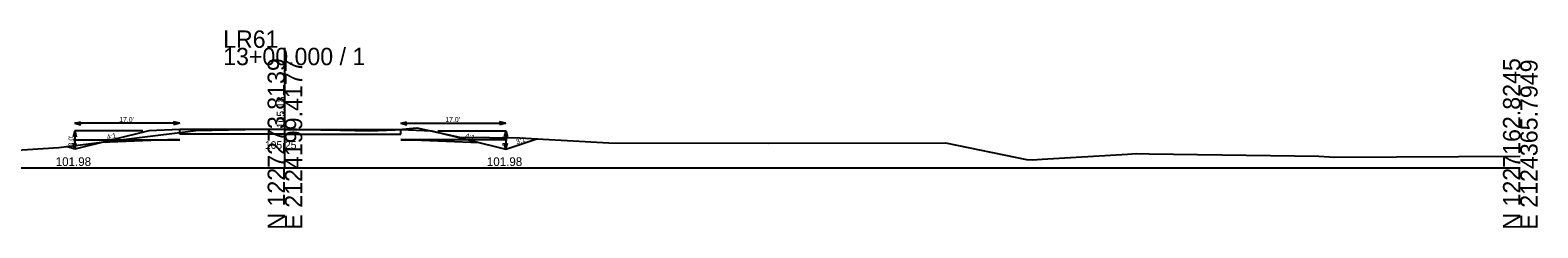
# Model space of a CAD drawing. Extents: x -26 to 1403, y -10 to 9574.
# Drawn here: x 1158.8 to 1402.8, y 2990.3 to 3022.2 of the extents above; entities that cross this region are included whole.
import ezdxf

# ---------------------------------------------------------------- set-up
doc = ezdxf.new("R2010")
doc.units = 0
for name, color, linetype in [('XS_CELL', 7, 'Continuous'), ('XS_P_FINISHED_GRADE', 7, 'Continuous'), ('XS_P_FINISHED_GRADE_ELEV_TX', 7, 'Continuous'), ('XS_P_SUBGRADE_GRANULAR', 7, 'Continuous'), ('XS_P_SUBGRADE_PAVEMENT', 7, 'Continuous'), ('XS_P_TX_CLEARZONE', 7, 'Continuous'), ('XS_P_TX_DCH', 7, 'Continuous'), ('XS_P_TX_FS_BS', 7, 'Continuous'), ('XS_X_GROUND', 7, 'Continuous'), ('XS_X_GROUND_TX', 7, 'Continuous')]:
    doc.layers.add(name, color=color, linetype=linetype)

msp = doc.modelspace()

# ---------------------------------------------------------------- linework, layer by layer
at = {"layer": 'XS_CELL'}
for p, q in [((1200, 3000), (1200, 3019.36)), ((1000, 3000), (1200, 3000)), ((1200, 3000), (1400, 3000))]:
    msp.add_line(p, q, dxfattribs=at)
at = {"layer": 'XS_P_FINISHED_GRADE'}
for p, q in [((1177.97, 3005.98), (1165.96, 3002.98)), ((1182.97, 3006.18), (1177.97, 3005.98)), ((1200, 3006.18), (1182.97, 3006.18)), ((1200, 3006.18), (1218.75, 3006.18)), ((1218.75, 3006.18), (1223.76, 3005.98)), ((1223.76, 3005.98), (1235.76, 3002.98)), ((1165.96, 3002.98), (1164.64, 3003.42)), ((1235.76, 3002.98), (1240.76, 3004.64))]:
    msp.add_line(p, q, dxfattribs=at)
at = {"layer": 'XS_P_SUBGRADE_GRANULAR'}
for p, q in [((1165.76, 3004.48), (1182.97, 3004.48)), ((1180.97, 3004.48), (1170.25, 3004.05)), ((1182.97, 3004.48), (1180.97, 3004.48)), ((1235.96, 3004.48), (1218.75, 3004.48)), ((1218.75, 3004.48), (1220.75, 3004.48)), ((1220.75, 3004.48), (1231.47, 3004.05))]:
    msp.add_line(p, q, dxfattribs=at)
at = {"layer": 'XS_P_SUBGRADE_PAVEMENT'}
for p, q in [((1182.97, 3005.43), (1182.97, 3006.18)), ((1200, 3005.43), (1182.97, 3005.43)), ((1200, 3005.43), (1218.75, 3005.43)), ((1218.75, 3005.43), (1218.75, 3006.18))]:
    msp.add_line(p, q, dxfattribs=at)
at = {"layer": 'XS_P_TX_CLEARZONE'}
for p, q in [((1165.96, 3007.18), (1166.96, 3007.43)), ((1165.96, 3007.18), (1166.96, 3006.93)), ((1182.97, 3007.18), (1165.96, 3007.18)), ((1182.97, 3007.18), (1181.97, 3007.43)), ((1182.97, 3007.18), (1181.97, 3006.93)), ((1218.75, 3007.18), (1219.75, 3007.43)), ((1218.75, 3007.18), (1219.75, 3006.93)), ((1218.75, 3007.18), (1235.76, 3007.18)), ((1235.76, 3007.18), (1234.76, 3007.43)), ((1235.76, 3007.18), (1234.76, 3006.93)), ((1165.96, 3005.98), (1165.71, 3004.98)), ((1165.96, 3005.98), (1166.21, 3004.98)), ((1165.96, 3005.98), (1165.96, 3002.98)), ((1176.97, 3005.98), (1165.96, 3005.98)), ((1224.76, 3005.98), (1235.76, 3005.98)), ((1235.76, 3005.98), (1235.51, 3004.98)), ((1235.76, 3005.98), (1235.76, 3002.98)), ((1235.76, 3005.98), (1236.01, 3004.98)), ((1165.96, 3002.98), (1165.71, 3003.98)), ((1165.96, 3002.98), (1166.21, 3003.98)), ((1235.76, 3002.98), (1235.51, 3003.98)), ((1235.76, 3002.98), (1236.01, 3003.98))]:
    msp.add_line(p, q, dxfattribs=at)
at = {"layer": 'XS_X_GROUND'}
for p, q in [((1165.61, 3003.53), (1185.59, 3006.01)), ((1185.59, 3006.01), (1196.22, 3006.2)), ((1196.22, 3006.2), (1199.86, 3006.26)), ((1199.86, 3006.26), (1205.81, 3006.14)), ((1205.81, 3006.14), (1206.62, 3006.12)), ((1206.62, 3006.12), (1213.76, 3005.97)), ((1213.76, 3005.97), (1217.87, 3006.13)), ((1217.87, 3006.13), (1221.37, 3006.45)), ((1221.37, 3006.45), (1228.27, 3004.93)), ((1228.27, 3004.93), (1237.95, 3004.8)), ((1237.95, 3004.8), (1252.46, 3004.02)), ((1146.03, 3002.14), (1163.42, 3003.27)), ((1163.42, 3003.27), (1165.61, 3003.53)), ((1252.46, 3004.02), (1278.34, 3003.94)), ((1278.34, 3003.94), (1306.95, 3004.02)), ((1306.95, 3004.02), (1320.05, 3001.35)), ((1336.43, 3002.2), (1337.82, 3002.32)), ((1337.82, 3002.32), (1339.91, 3002.26)), ((1320.05, 3001.35), (1321.04, 3001.28)), ((1321.04, 3001.28), (1322.6, 3001.4)), ((1322.6, 3001.4), (1336.43, 3002.2)), ((1339.91, 3002.26), (1367.4, 3001.86)), ((1367.4, 3001.86), (1369.97, 3001.71)), ((1369.97, 3001.71), (1400, 3001.87))]:
    msp.add_line(p, q, dxfattribs=at)

# ---------------------------------------------------------------- texts
at = {"layer": 'XS_CELL'}
for s, p in [('LR61', (1190, 3019.36)), ('13+00.000 / 1', (1190, 3016.56))]:
    msp.add_text(s, height=2.8, dxfattribs=at).set_placement(p)
for s, p in [('N 1227273.8139', (1200, 2990)), ('E 2124199.4177', (1202.8, 2990)), ('N 1227162.8245', (1400, 2990)), ('E 2124365.7949', (1402.8, 2990))]:
    msp.add_text(s, height=2.8, rotation=90, dxfattribs=at).set_placement(p)
at = {"layer": 'XS_P_FINISHED_GRADE_ELEV_TX'}
msp.add_text('105.18', height=1.25, rotation=90, dxfattribs=at).set_placement((1199.93, 3006.39))
at = {"layer": 'XS_P_TX_CLEARZONE'}
for p in [(1173.18, 3007.38), (1225.97, 3007.38)]:
    msp.add_text("17.0'", height=0.8, dxfattribs=at).set_placement(p)
for p in [(1165.76, 3003.45), (1235.96, 3003.45)]:
    msp.add_text("3.0'", height=0.8, rotation=90, dxfattribs=at).set_placement(p)
at = {"layer": 'XS_P_TX_DCH'}
for p in [(1162.89, 3000.28), (1232.69, 3000.28)]:
    msp.add_text('101.98', height=1.4, dxfattribs=at).set_placement(p)
at = {"layer": 'XS_P_TX_FS_BS'}
for s, rotation, p in [('4:1', 14.0343, (1171.26, 3004.5)), ('4:1', 345.9663, (1229.15, 3004.83)), ('3:1', 18.4317, (1237.55, 3003.78))]:
    msp.add_text(s, height=0.8, rotation=rotation, dxfattribs=at).set_placement(p)
at = {"layer": 'XS_X_GROUND_TX'}
msp.add_text('105.25', height=1.25, rotation=360, dxfattribs=at).set_placement((1196.76, 3003.04))

doc.saveas('drawing.dxf')
